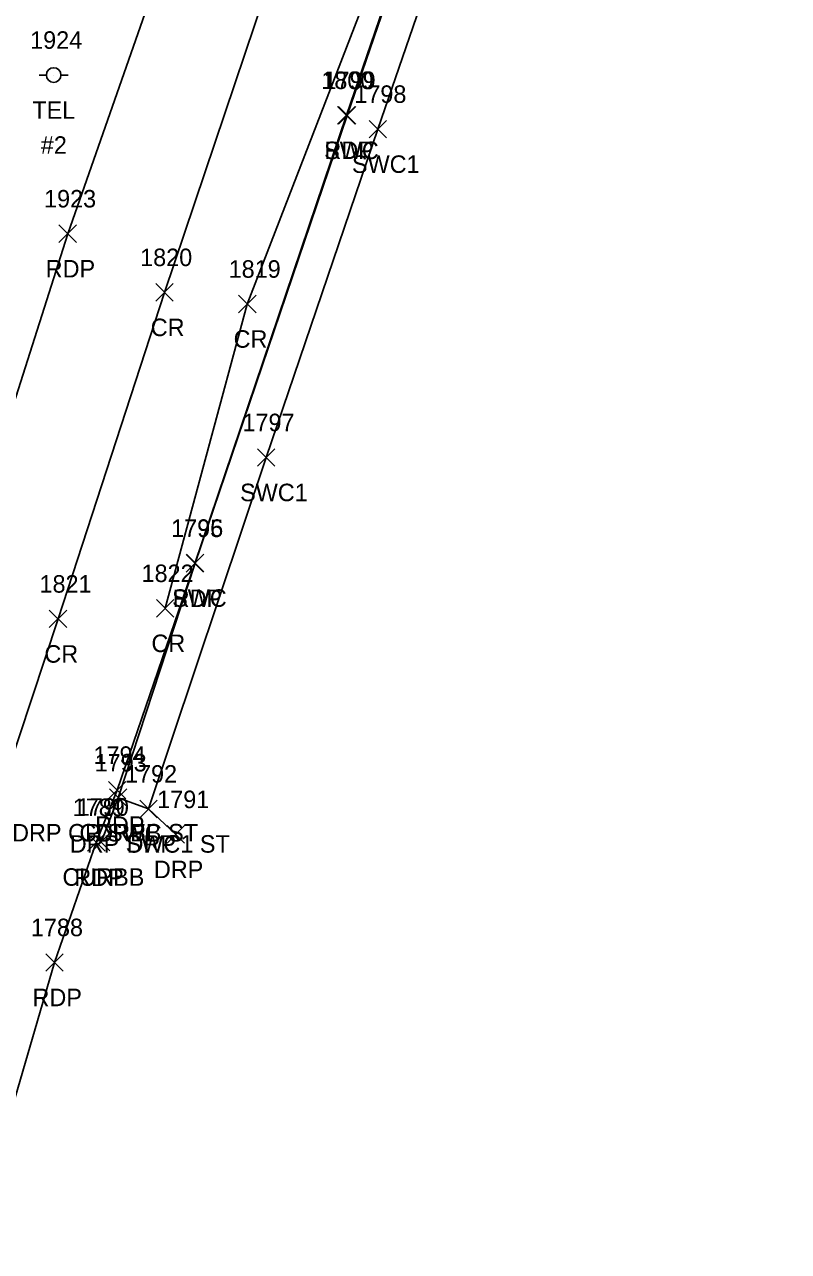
# Model space of a CAD drawing. Extents: x 1769141 to 1770817, y 735471 to 742405.
# Drawn here: x 1770309 to 1770396.2, y 742041.1 to 742181.3 of the extents above; entities that cross this region are included whole.
import ezdxf

# ---------------------------------------------------------------- set-up
doc = ezdxf.new("R2010")
doc.units = 0
for name, color, linetype in [('P_A', 7, 'Continuous'), ('P_I', 7, 'Continuous'), ('P_TIC', 7, 'Continuous'), ('PET', 7, 'Continuous'), ('PRC', 7, 'Continuous'), ('R_A', 7, 'Continuous'), ('R_I', 7, 'Continuous'), ('R_TIC', 7, 'Continuous'), ('RC', 7, 'Continuous'), ('RDP', 7, 'Continuous'), ('RSW', 7, 'Continuous'), ('U_A', 7, 'Continuous'), ('U_C', 7, 'Continuous'), ('U_I', 7, 'Continuous'), ('UP', 7, 'Continuous')]:
    doc.layers.add(name, color=color, linetype=linetype)

msp = doc.modelspace()

# ---------------------------------------------------------------- linework, layer by layer
at = {"layer": 'P_TIC'}
for points in [[(1770344.72, 742169.91), (1770346.72, 742171.91)], [(1770346.72, 742169.91), (1770344.72, 742171.91)], [(1770312.88, 742156.38), (1770314.88, 742158.38)], [(1770314.88, 742156.38), (1770312.88, 742158.38)], [(1770323.94, 742149.68), (1770325.94, 742151.68)], [(1770325.94, 742149.68), (1770323.94, 742151.68)], [(1770333.4, 742148.35), (1770335.4, 742150.35)], [(1770335.4, 742148.35), (1770333.4, 742150.35)], [(1770327.4, 742118.72), (1770329.4, 742120.72)], [(1770329.4, 742118.72), (1770327.4, 742120.72)], [(1770324.02, 742113.58), (1770326.02, 742115.58)], [(1770326.02, 742113.58), (1770324.02, 742115.58)], [(1770311.78, 742112.37), (1770313.78, 742114.37)], [(1770313.78, 742112.37), (1770311.78, 742114.37)], [(1770318.53, 742092.81), (1770320.53, 742094.81)], [(1770320.53, 742092.81), (1770318.53, 742094.81)], [(1770316.15, 742086.84), (1770318.15, 742088.84)], [(1770318.15, 742086.84), (1770316.15, 742088.84)], [(1770311.37, 742073.12), (1770313.37, 742075.12)], [(1770313.37, 742073.12), (1770311.37, 742075.12)]]:
    msp.add_lwpolyline(points, dxfattribs=at)
at = {"layer": 'PET'}
for points in [[(1770272.7, 742023.54), (1770282.64, 742061.02), (1770293.57, 742093.79), (1770304.4, 742127.71), (1770313.88, 742157.38), (1770333.72, 742213.99), (1770354.85, 742269.34), (1770368.55, 742301.73), (1770378.75, 742329.81), (1770392.05, 742361.37)], [(1770296.04, 742015.55), (1770303.14, 742042.61), (1770312.37, 742074.12), (1770317.15, 742087.84), (1770319.53, 742093.81), (1770328.4, 742119.72), (1770345.72, 742170.91), (1770359.21, 742210.32), (1770377.16, 742259.11), (1770392.46, 742300.59)]]:
    msp.add_lwpolyline(points, dxfattribs=at)
at = {"layer": 'PRC'}
for points in [[(1770386.13, 742315.42), (1770368.53, 742271.05), (1770352, 742227.48), (1770338.73, 742191.59), (1770324.94, 742150.68), (1770312.78, 742113.37), (1770302.28, 742081.69), (1770292.17, 742047.68), (1770283.01, 742015.74), (1770275.68, 741981.9), (1770269.49, 741954.54), (1770264.41, 741931.75), (1770261.81, 741920.34)], [(1770394.22, 742311.3), (1770377.82, 742266.18), (1770362.64, 742225.34), (1770348.95, 742186.97), (1770334.4, 742149.35), (1770325.02, 742114.58)]]:
    msp.add_lwpolyline(points, dxfattribs=at)
at = {"layer": 'R_TIC'}
for points in [[(1770344.82, 742169.9), (1770346.82, 742171.9)], [(1770346.82, 742169.9), (1770344.82, 742171.9)], [(1770348.32, 742168.33), (1770350.32, 742170.33)], [(1770350.32, 742168.33), (1770348.32, 742170.33)], [(1770335.55, 742130.82), (1770337.55, 742132.82)], [(1770337.55, 742130.82), (1770335.55, 742132.82)], [(1770327.45, 742118.75), (1770329.45, 742120.75)], [(1770329.45, 742118.75), (1770327.45, 742120.75)], [(1770318.65, 742091.94), (1770320.65, 742093.94)], [(1770320.65, 742091.94), (1770318.65, 742093.94)], [(1770318.65, 742091.94), (1770320.65, 742093.94)], [(1770320.65, 742091.94), (1770318.65, 742093.94)], [(1770318.65, 742091.94), (1770320.65, 742093.94)], [(1770320.65, 742091.94), (1770318.65, 742093.94)], [(1770322.12, 742090.66), (1770324.12, 742092.66)], [(1770324.12, 742090.66), (1770322.12, 742092.66)], [(1770322.12, 742090.66), (1770324.12, 742092.66)], [(1770324.12, 742090.66), (1770322.12, 742092.66)], [(1770325.24, 742087.75), (1770327.24, 742089.75)], [(1770327.24, 742087.75), (1770325.24, 742089.75)], [(1770316.7, 742086.88), (1770318.7, 742088.88)], [(1770318.7, 742086.88), (1770316.7, 742088.88)]]:
    msp.add_lwpolyline(points, dxfattribs=at)
at = {"layer": 'RC'}
msp.add_lwpolyline([(1770317.7, 742087.88), (1770319.65, 742092.94)], dxfattribs=at)
at = {"layer": 'RDP'}
msp.add_lwpolyline([(1770326.24, 742088.75), (1770323.12, 742091.66), (1770319.65, 742092.94)], dxfattribs=at)
at = {"layer": 'RSW'}
for points in [[(1770319.65, 742092.94), (1770328.45, 742119.75), (1770345.82, 742170.9), (1770359.28, 742210.21), (1770377.48, 742258.88), (1770392.51, 742300.46)], [(1770323.12, 742091.66), (1770336.55, 742131.82), (1770349.32, 742169.33), (1770362.98, 742209.08), (1770380.8, 742257.79), (1770396.24, 742299.16)]]:
    msp.add_lwpolyline(points, dxfattribs=at)
at = {"layer": 'UP'}
for p, q in [((1770310.62, 742175.51), (1770311.45, 742175.51)), ((1770312.28, 742175.51), (1770312.28, 742175.51)), ((1770313.95, 742175.51), (1770313.11, 742175.51)), ((1770313.11, 742175.51), (1770313.11, 742175.51)), ((1770313.95, 742175.51), (1770313.95, 742175.51))]:
    msp.add_line(p, q, dxfattribs=at)
msp.add_circle((1770312.28, 742175.51), 0.833, dxfattribs=at)

# ---------------------------------------------------------------- texts
at = {"layer": 'P_A'}
for s, p in [('RDP', (1770343.21, 742165.91)), ('RDP', (1770311.37, 742152.38)), ('CR', (1770323.37, 742145.68)), ('CR', (1770332.84, 742144.35)), ('RDP', (1770325.88, 742114.72)), ('CR', (1770311.22, 742108.37)), ('CR', (1770323.45, 742109.58)), ('RDP', (1770317.01, 742088.81)), ('RDP', (1770314.64, 742082.84)), ('RDP', (1770309.86, 742069.12))]:
    msp.add_text(s, height=2, dxfattribs=at).set_placement(p)
at = {"layer": 'P_I'}
for s, p in [('1800', (1770342.86, 742173.91)), ('1923', (1770311.18, 742160.38)), ('1820', (1770322.16, 742153.68)), ('1819', (1770332.27, 742152.35)), ('1795', (1770325.7, 742122.72)), ('1822', (1770322.32, 742117.58)), ('1821', (1770310.66, 742116.37)), ('1794', (1770316.83, 742096.81)), ('1789', (1770314.45, 742090.84)), ('1788', (1770309.68, 742077.12))]:
    msp.add_text(s, height=2, dxfattribs=at).set_placement(p)
at = {"layer": 'R_A'}
for s, p in [('SWC', (1770343.18, 742165.9)), ('SWC1', (1770346.36, 742164.33)), ('SWC1', (1770333.58, 742126.82)), ('SWC', (1770325.81, 742114.75)), ('DRP CP SWC ST', (1770307.53, 742087.94)), ('CURBB', (1770315.23, 742087.94)), ('DRP', (1770317.14, 742087.94)), ('DRP SWC1 ST', (1770314.12, 742086.66)), ('DRP', (1770320.61, 742086.66)), ('DRP', (1770323.73, 742083.75)), ('CURBB', (1770313.28, 742082.88))]:
    msp.add_text(s, height=2, dxfattribs=at).set_placement(p)
at = {"layer": 'R_I'}
for s, p in [('1799', (1770343.12, 742173.9)), ('1798', (1770346.63, 742172.33)), ('1797', (1770333.85, 742134.82)), ('1796', (1770325.7, 742122.75)), ('1793', (1770316.96, 742095.94)), ('1793', (1770316.96, 742095.94)), ('1793', (1770316.96, 742095.94)), ('1792', (1770320.43, 742094.66)), ('1792', (1770320.43, 742094.66)), ('1791', (1770324.11, 742091.75)), ('1790', (1770314.92, 742090.88))]:
    msp.add_text(s, height=2, dxfattribs=at).set_placement(p)
at = {"layer": 'U_A'}
msp.add_text('TEL', height=2, dxfattribs=at).set_placement((1770309.84, 742170.51))
at = {"layer": 'U_C'}
msp.add_text('#2', height=2, dxfattribs=at).set_placement((1770310.81, 742166.51))
at = {"layer": 'U_I'}
msp.add_text('1924', height=2, dxfattribs=at).set_placement((1770309.59, 742178.51))

doc.saveas('drawing.dxf')
